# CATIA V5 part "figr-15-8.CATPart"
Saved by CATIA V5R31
Part number: Part1
Bounding box of the stored display mesh (mm): x -50 to 50, y -32.5 to 33.5, z -52 to 1
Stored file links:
  D:\PROJECTS\Project 2021\US EDITION\CATIA V5 6R 2021\Resources\Part Files\c15_catia_v5_6r2021_prt\figr-15-8.CATPart
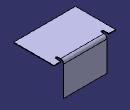
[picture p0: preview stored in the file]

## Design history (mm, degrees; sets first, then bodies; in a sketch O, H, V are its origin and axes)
SheetMetalParameters1: Thickness 1, BendRadius 4, KFactor 0.475772 {= log(min(100,max(20*SheetMetalParameters1.BendRadius,SheetMetalParameters1.Thickness)/SheetMetalParameters1.Thickness))/log(100)/2}, ReliefRadialLength 4, ReliefAxialLength 4, MinimumBendRadius 0
Body1 (main body)
  Sketch1 on xy-plane, origin (0, 0, 0), H (1, 0, 0), V (0, 1, 0)
    line L1 (-50, 32.5) -> (50, 32.5)
    line L2 (50, 32.5) -> (50, -32.5)
    line L3 (50, -32.5) -> (-50, -32.5)
    line L4 (-50, -32.5) -> (-50, 32.5)
    length L1 = 100
    length L2 = 65
    horizontal: L1 H, L3 H
    vertical: L2 V, L4 V
    symmetry: L4 L2 V, L1 L3 H
  Wall1: Thickness 1, Profile Sketch1
  d_NewWallOnEdge1: NewWallOnEdge_Edge edge [face of Wall1 | face of Wall1], NewWallOnEdge_Length 53, NewWallOnEdge_HeightLimitOffset 0, NewWallOnEdge_WidthOffset1 -15, NewWallOnEdge_WidthOffset2 -15, NewWallOnEdge_Angle 90, NewWallOnEdge_BendRadiusValue 4 {= SheetMetalParameters1.BendRadius}, NewWallOnEdge_BendTable SheetMetalParameters1, KFacteur 0.475772 {= log(min(100,max(20*d_NewWallOnEdge1.Radius,SheetMetalParameters1.Thickness)/SheetMetalParameters1.Thickness))/log(100)/2}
